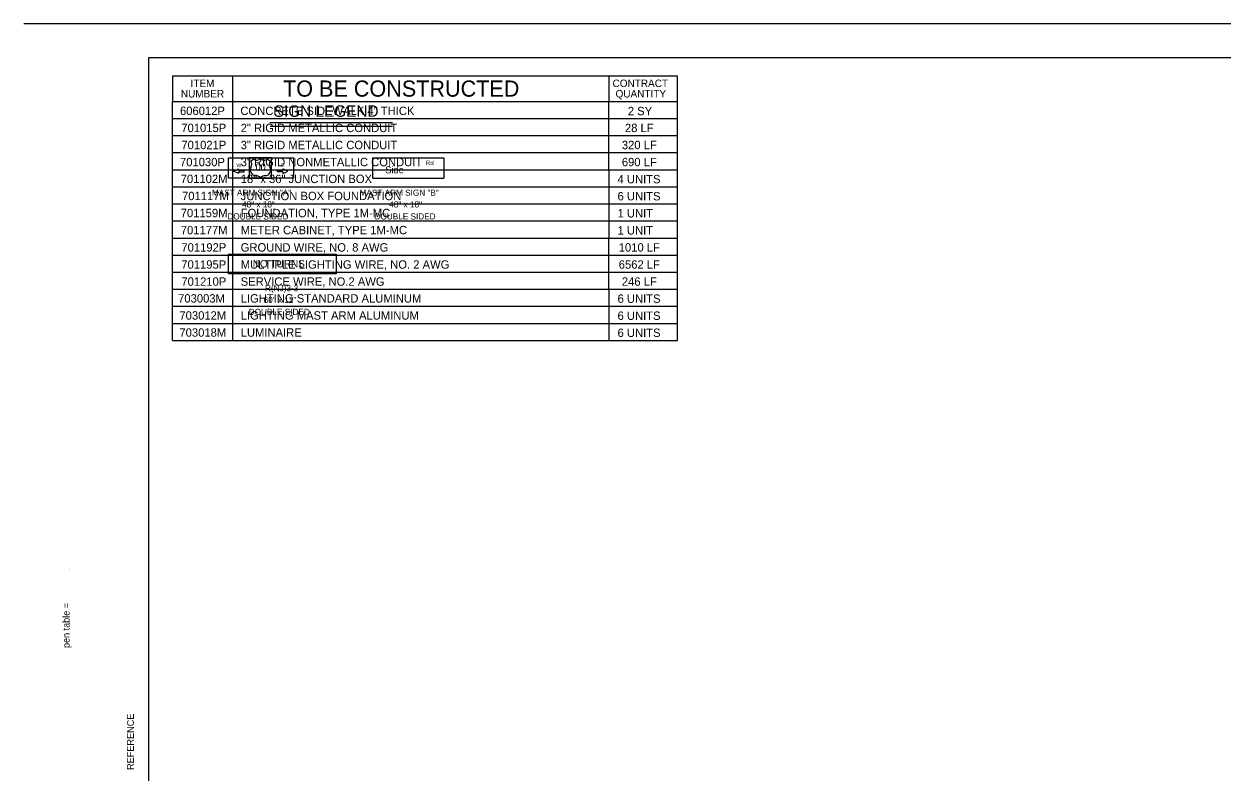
# Model space of a CAD drawing. Extents: x 488740 to 507913, y 466518 to 497949.
# Drawn here: x 507907.724 to 507909.198, y 496047.319 to 496048.24 of the extents above; entities that cross this region are included whole.
import ezdxf

# ---------------------------------------------------------------- set-up
doc = ezdxf.new("R2010")
doc.units = 0
for name, color, linetype in [('1', 7, 'Continuous'), ('12', 7, 'Continuous'), ('9', 7, 'Continuous')]:
    doc.layers.add(name, color=color, linetype=linetype)

msp = doc.modelspace()

# ---------------------------------------------------------------- linework, layer by layer
at = {"layer": '1'}
for p, q in [((507910.6358, 496048.2395), (507907.7241, 496048.2395)), ((507907.8773, 496048.1978), (507907.8773, 496046.4478)), ((507910.6273, 496048.1978), (507907.8773, 496048.1978))]:
    msp.add_line(p, q, dxfattribs=at)
at = {"layer": '12'}
for p, q in [((507907.9068, 496048.1757), (507908.5278, 496048.1757)), ((507907.9068, 496048.1757), (507907.9068, 496048.1442)), ((507907.9809, 496048.1757), (507907.9809, 496048.1442)), ((507908.4439, 496048.1757), (507908.4439, 496048.1442)), ((507908.4439, 496048.1757), (507908.4439, 496048.1442)), ((507908.5278, 496048.1757), (507908.5278, 496048.1442)), ((507908.5278, 496048.1757), (507908.5278, 496048.1442)), ((507907.9068, 496048.1442), (507908.5278, 496048.1442)), ((507907.9068, 496048.1232), (507907.9068, 496048.1442)), ((507907.9813, 496048.1232), (507907.9813, 496048.1442)), ((507908.4439, 496048.1232), (507908.4439, 496048.1442)), ((507908.5282, 496048.1232), (507908.5282, 496048.1442)), ((507907.9068, 496048.1022), (507907.9068, 496048.1232)), ((507907.9068, 496048.1022), (507907.9068, 496048.1232)), ((507907.9068, 496048.1232), (507908.5282, 496048.1232)), ((507907.9813, 496048.1022), (507907.9813, 496048.1232)), ((507907.9813, 496048.1022), (507907.9813, 496048.1232)), ((507908.4439, 496048.1022), (507908.4439, 496048.1232)), ((507908.5282, 496048.1022), (507908.5282, 496048.1232)), ((507907.9068, 496048.1022), (507908.5282, 496048.1022)), ((507907.9068, 496048.0812), (507907.9068, 496048.1022)), ((507907.9068, 496048.0812), (507907.9068, 496048.1022)), ((507907.9813, 496048.0812), (507907.9813, 496048.1022)), ((507907.9813, 496048.0812), (507907.9813, 496048.1022)), ((507908.4439, 496048.0812), (507908.4439, 496048.1022)), ((507908.4439, 496048.0812), (507908.4439, 496048.1022)), ((507908.5282, 496048.0812), (507908.5282, 496048.1022)), ((507908.5282, 496048.0812), (507908.5282, 496048.1022)), ((507907.9068, 496048.0812), (507908.5282, 496048.0812)), ((507907.9068, 496048.0602), (507907.9068, 496048.0812)), ((507907.9068, 496048.0602), (507907.9068, 496048.0812)), ((507907.9813, 496048.0602), (507907.9813, 496048.0812)), ((507907.9813, 496048.0602), (507907.9813, 496048.0812)), ((507908.4439, 496048.0602), (507908.4439, 496048.0812)), ((507908.4439, 496048.0602), (507908.4439, 496048.0812)), ((507908.5282, 496048.0602), (507908.5282, 496048.0812)), ((507908.5282, 496048.0602), (507908.5282, 496048.0812)), ((507907.9068, 496048.0602), (507908.5282, 496048.0602)), ((507907.9068, 496048.0392), (507907.9068, 496048.0602)), ((507907.9813, 496048.0392), (507907.9813, 496048.0602)), ((507908.4442, 496048.0392), (507908.4442, 496048.0602)), ((507908.5282, 496048.0392), (507908.5282, 496048.0602)), ((507907.9068, 496048.0392), (507908.5282, 496048.0392)), ((507907.9068, 496048.0182), (507907.9068, 496048.0392)), ((507907.9813, 496048.0182), (507907.9813, 496048.0392)), ((507908.4442, 496048.0182), (507908.4442, 496048.0392)), ((507908.5282, 496048.0182), (507908.5282, 496048.0392)), ((507907.9068, 496048.0182), (507908.5282, 496048.0182)), ((507907.9068, 496047.9972), (507907.9068, 496048.0182)), ((507907.9813, 496047.9972), (507907.9813, 496048.0182)), ((507908.4442, 496047.9972), (507908.4442, 496048.0182)), ((507908.5282, 496047.9972), (507908.5282, 496048.0182)), ((507907.9068, 496047.9972), (507908.5282, 496047.9972)), ((507907.9068, 496047.9762), (507907.9068, 496047.9972)), ((507907.9813, 496047.9762), (507907.9813, 496047.9972)), ((507908.4442, 496047.9762), (507908.4442, 496047.9972)), ((507908.5282, 496047.9762), (507908.5282, 496047.9972)), ((507907.9068, 496047.9762), (507908.5282, 496047.9762)), ((507907.9068, 496047.9552), (507907.9068, 496047.9762)), ((507907.9068, 496047.9552), (507907.9068, 496047.9762)), ((507907.9813, 496047.9552), (507907.9813, 496047.9762)), ((507907.9813, 496047.9552), (507907.9813, 496047.9762)), ((507908.4439, 496047.9552), (507908.4439, 496047.9762)), ((507908.5282, 496047.9552), (507908.5282, 496047.9762)), ((507907.9068, 496047.9342), (507907.9068, 496047.9552)), ((507907.9068, 496047.9552), (507908.5282, 496047.9552)), ((507907.9813, 496047.9342), (507907.9813, 496047.9552)), ((507908.4439, 496047.9342), (507908.4439, 496047.9552)), ((507908.5282, 496047.9342), (507908.5282, 496047.9552)), ((507907.9068, 496047.9342), (507908.5282, 496047.9342)), ((507907.9068, 496047.9132), (507907.9068, 496047.9342)), ((507907.9068, 496047.9132), (507907.9068, 496047.9342)), ((507907.9813, 496047.9132), (507907.9813, 496047.9342)), ((507907.9813, 496047.9132), (507907.9813, 496047.9342)), ((507908.4439, 496047.9132), (507908.4439, 496047.9342)), ((507908.5282, 496047.9132), (507908.5282, 496047.9342)), ((507907.9068, 496047.9132), (507908.5282, 496047.9132)), ((507907.9068, 496047.8922), (507907.9068, 496047.9132)), ((507907.9813, 496047.8922), (507907.9813, 496047.9132)), ((507908.4442, 496047.8922), (507908.4442, 496047.9132)), ((507908.5282, 496047.8922), (507908.5282, 496047.9132)), ((507907.9068, 496047.8922), (507908.5282, 496047.8922)), ((507907.9068, 496047.8712), (507907.9068, 496047.8922)), ((507907.9813, 496047.8712), (507907.9813, 496047.8922)), ((507908.4442, 496047.8712), (507908.4442, 496047.8922)), ((507908.5282, 496047.8712), (507908.5282, 496047.8922)), ((507907.9068, 496047.8712), (507908.5282, 496047.8712)), ((507907.9068, 496047.8502), (507907.9068, 496047.8712)), ((507907.9813, 496047.8502), (507907.9813, 496047.8712)), ((507908.4442, 496047.8502), (507908.4442, 496047.8712)), ((507908.5282, 496047.8502), (507908.5282, 496047.8712)), ((507907.9068, 496047.8502), (507908.5282, 496047.8502))]:
    msp.add_line(p, q, dxfattribs=at)
at = {"layer": '9'}
for p, q in [((507908.0268, 496048.1182), (507908.1774, 496048.1182)), ((507908.0269, 496048.1138), (507908.1775, 496048.1138)), ((507908.0032, 496048.0707), (507908.0067, 496048.0736)), ((507908.0236, 496048.0736), (507908.0271, 496048.0707)), ((507908.1529, 496048.0748), (507908.1529, 496048.0499)), ((507908.1529, 496048.0748), (507908.2408, 496048.0748)), ((507908.1529, 496048.0748), (507908.2408, 496048.0748)), ((507908.2408, 496048.0748), (507908.2408, 496048.0499)), ((507908.0151, 496048.0498), (507908.0151, 496048.0504)), ((507908.0153, 496048.0504), (507908.0153, 496048.0498)), ((507908.1529, 496048.0499), (507908.2408, 496048.0499))]:
    msp.add_line(p, q, dxfattribs=at)
for points in [[(507907.9757, 496048.0748), (507908.0558, 496048.0748), (507908.0558, 496048.0499), (507907.9757, 496048.0499)], [(507907.9888, 496048.0575), (507907.9887, 496048.0575), (507907.9886, 496048.0575), (507907.9885, 496048.0575), (507907.9883, 496048.0574), (507907.9882, 496048.0573), (507907.9882, 496048.0573), (507907.9882, 496048.0563), (507907.9882, 496048.0563), (507907.9881, 496048.0562), (507907.9881, 496048.0562), (507907.988, 496048.0561), (507907.9879, 496048.0561), (507907.9878, 496048.056), (507907.9876, 496048.056), (507907.9875, 496048.056), (507907.9872, 496048.0561), (507907.9821, 496048.0585), (507907.9874, 496048.0608), (507907.9875, 496048.0609), (507907.9876, 496048.0609), (507907.9878, 496048.0609), (507907.988, 496048.0609), (507907.9881, 496048.0608), (507907.9882, 496048.0608), (507907.9882, 496048.0607), (507907.9883, 496048.0606), (507907.9883, 496048.0597), (507907.9883, 496048.0596), (507907.9883, 496048.0595), (507907.9884, 496048.0595), (507907.9884, 496048.0595), (507907.9885, 496048.0594), (507907.9886, 496048.0594), (507907.9886, 496048.0594), (507907.9889, 496048.0594)], [(507907.9889, 496048.0575), (507907.995, 496048.0575), (507907.995, 496048.0594), (507907.9889, 496048.0594)], [(507908.042, 496048.0575), (507908.0359, 496048.0575), (507908.0359, 496048.0594), (507908.042, 496048.0594)], [(507908.0421, 496048.0575), (507908.0422, 496048.0575), (507908.0423, 496048.0575), (507908.0424, 496048.0574), (507908.0426, 496048.0574), (507908.0427, 496048.0573), (507908.0427, 496048.0573), (507908.0427, 496048.0563), (507908.0427, 496048.0562), (507908.0428, 496048.0562), (507908.0428, 496048.0561), (507908.0429, 496048.0561), (507908.043, 496048.0561), (507908.0431, 496048.056), (507908.0433, 496048.056), (507908.0435, 496048.056), (507908.0437, 496048.0561), (507908.0489, 496048.0584), (507908.0435, 496048.0608), (507908.0435, 496048.0609), (507908.0433, 496048.0609), (507908.0431, 496048.0609), (507908.0429, 496048.0609), (507908.0428, 496048.0608), (507908.0427, 496048.0607), (507908.0427, 496048.0606), (507908.0426, 496048.0606), (507908.0426, 496048.0597), (507908.0426, 496048.0596), (507908.0426, 496048.0595), (507908.0425, 496048.0594), (507908.0425, 496048.0594), (507908.0424, 496048.0594), (507908.0423, 496048.0594), (507908.0423, 496048.0594), (507908.042, 496048.0594)], [(507907.9757, 496047.9564), (507908.1083, 496047.9564), (507908.1083, 496047.9321), (507907.9757, 496047.9321)]]:
    msp.add_lwpolyline(points, close=True, dxfattribs=at)
msp.add_lwpolyline([(507908.0153, 496048.0498), (507908.0289, 496048.0498), (507908.0289, 496048.0748), (507908.0014, 496048.0748), (507908.0014, 496048.0498), (507908.0151, 496048.0498)], dxfattribs=at)
for centre, radius, start, end in [((507907.9987, 496048.0669), 0.00591, 318.9676, 41.0324), ((507908.0106, 496048.0776), 0.00557, 226.1378, 324.9761), ((507908.0197, 496048.0776), 0.00557, 215.0239, 313.8622), ((507908.0316, 496048.0669), 0.00591, 138.9676, 221.0324), ((507908.0098, 496048.0601), 0.00724, 156.1093, 263.197), ((507908.0081, 496048.0419), 0.0111, 50.6358, 85.3253), ((507908.0223, 496048.0419), 0.0111, 94.6747, 129.3642), ((507908.0205, 496048.0601), 0.00724, 276.803, 23.8907)]:
    msp.add_arc(centre, radius, start, end, dxfattribs=at)

# ---------------------------------------------------------------- texts
at = {"layer": '1'}
for s, height, p in [('...................pentable..................', 0.00012, (507907.7802, 496047.5674)), ('pen table =', 0.008335, (507907.7802, 496047.4719)), ('REFERENCE                                                              ', 0.0084, (507907.8593, 496047.3219))]:
    msp.add_text(s, height=height, rotation=90, dxfattribs=at).set_placement(p)
at = {"layer": '12'}
for s, height, p in [('ITEM', 0.00919, (507907.9291, 496048.1619)), ('TO BE CONSTRUCTED', 0.01987, (507908.0429, 496048.1501)), ('CONTRACT', 0.00919, (507908.4484, 496048.1619)), ('NUMBER', 0.00919, (507907.9172, 496048.1491)), ('QUANTITY', 0.00919, (507908.4521, 496048.1491)), ('606012P', 0.01032, (507907.9161, 496048.1275)), ('CONCRETE SIDEWALK 4" THICK', 0.010317, (507907.9904, 496048.1275)), ('   2 SY', 0.01032, (507908.4557, 496048.1272)), ('701015P', 0.01032, (507907.9177, 496048.1065)), ('2" RIGID METALLIC CONDUIT', 0.010317, (507907.9908, 496048.1065)), ('  28 LF', 0.01032, (507908.456, 496048.1065)), ('701021P', 0.01032, (507907.9178, 496048.0855)), ('3" RIGID METALLIC CONDUIT', 0.010317, (507907.9908, 496048.0855)), (' 320 LF', 0.01032, (507908.456, 496048.0855)), ('701030P', 0.01032, (507907.9161, 496048.0645)), ('3" RIGID NONMETALLIC CONDUIT', 0.010317, (507907.9908, 496048.0645)), (' 690 LF', 0.01032, (507908.456, 496048.0645)), ('701102M', 0.01032, (507907.917, 496048.0438)), ('18" x 36" JUNCTION BOX', 0.010317, (507907.9908, 496048.0438)), (' 4 UNITS', 0.01032, (507908.4507, 496048.0435)), ('701117M', 0.01032, (507907.9186, 496048.0228)), ('JUNCTION BOX FOUNDATION', 0.010317, (507907.9908, 496048.0228)), (' 6 UNITS', 0.01032, (507908.4507, 496048.0225)), ('701159M', 0.01032, (507907.917, 496048.0018)), ('FOUNDATION, TYPE 1M-MC', 0.010317, (507907.9908, 496048.0018)), (' 1 UNIT ', 0.01032, (507908.4507, 496048.0015)), ('701177M', 0.01032, (507907.9171, 496047.9808)), ('METER CABINET, TYPE 1M-MC', 0.010317, (507907.9908, 496047.9808)), (' 1 UNIT ', 0.01032, (507908.4507, 496047.9805)), ('701192P', 0.01032, (507907.9178, 496047.9595)), ('GROUND WIRE, NO. 8 AWG', 0.010317, (507907.9908, 496047.9595)), ('1010 LF', 0.01032, (507908.456, 496047.9595)), ('701195P', 0.01032, (507907.9177, 496047.9385)), ('MULTIPLE LIGHTING WIRE, NO. 2 AWG', 0.010317, (507907.9908, 496047.9385)), ('6562 LF', 0.01032, (507908.456, 496047.9385)), ('701210P', 0.01032, (507907.9178, 496047.9175)), ('SERVICE WIRE, NO.2 AWG', 0.010317, (507907.9908, 496047.9175)), (' 246 LF', 0.01032, (507908.456, 496047.9175)), ('703003M', 0.01032, (507907.9138, 496047.8968)), ('LIGHTING STANDARD ALUMINUM', 0.010317, (507907.9908, 496047.8968)), (' 6 UNITS', 0.01032, (507908.4507, 496047.8965)), ('703012M', 0.01032, (507907.9154, 496047.8758)), ('LIGHTING MAST ARM ALUMINUM', 0.010317, (507907.9908, 496047.8758)), (' 6 UNITS', 0.01032, (507908.4507, 496047.8755)), ('703018M', 0.01032, (507907.9154, 496047.8548)), ('LUMINAIRE', 0.01032, (507907.9908, 496047.8548)), (' 6 UNITS', 0.01032, (507908.4507, 496047.8545))]:
    msp.add_text(s, height=height, dxfattribs=at).set_placement(p)
at = {"layer": '9'}
for s, height, p in [('SIGN LEGEND', 0.014108, (507908.0315, 496048.1253)), ('W', 0.00468, (507907.9855, 496048.0634)), ('00', 0.00831, (507908.0092, 496048.0594)), ('E', 0.00468, (507908.0405, 496048.0634)), ('Side', 0.00862, (507908.1686, 496048.0558)), ('Rd', 0.00563, (507908.2185, 496048.0659)), ('MAST ARM SIGN "A"', 0.007545, (507907.9554, 496048.0282)), ('MAST ARM SIGN "B"', 0.007545, (507908.1371, 496048.0282)), ('48" x 18"', 0.00755, (507907.9925, 496048.0138)), ('48" x 18"', 0.00755, (507908.1736, 496048.0138)), ('DOUBLE SIDED', 0.007545, (507907.9744, 496047.999)), ('DOUBLE SIDED', 0.007545, (507908.1555, 496047.999)), ('NO TURNS', 0.00919, (507908.0056, 496047.94)), ('R(NJ)3-3', 0.00755, (507908.0207, 496047.9108)), ('60" x 12"', 0.00755, (507908.019, 496047.8963)), ('DOUBLE SIDED', 0.007545, (507908.0007, 496047.8816))]:
    msp.add_text(s, height=height, dxfattribs=at).set_placement(p)

doc.saveas('drawing.dxf')
